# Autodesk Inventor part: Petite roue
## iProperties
Author: patrick
Shininess: 20.0
Angle Display Precision: 2
Document Length Units: 11269
Document Angle Units: 11283
Document Time Units: 11279
Document Mass Units: 11290
Document Length Units Precision: 3
Document Angle Units Precision: 2
Compacted: True
PropertySet Name: _Private Model Information
Created: 2002-10
Part Number: Petite roue
Material: Par défaut
Document SubType Name: Modélisation
Designer: patrick
Control State: 0
Master: False
Checked Out: False
PropertySet Name: Design Tracking Control
Density: 0.0
Volumn: 0.0
Area: 0.0
PropertySet Name: Model Information
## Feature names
1. Révolution1 [Revolution]
